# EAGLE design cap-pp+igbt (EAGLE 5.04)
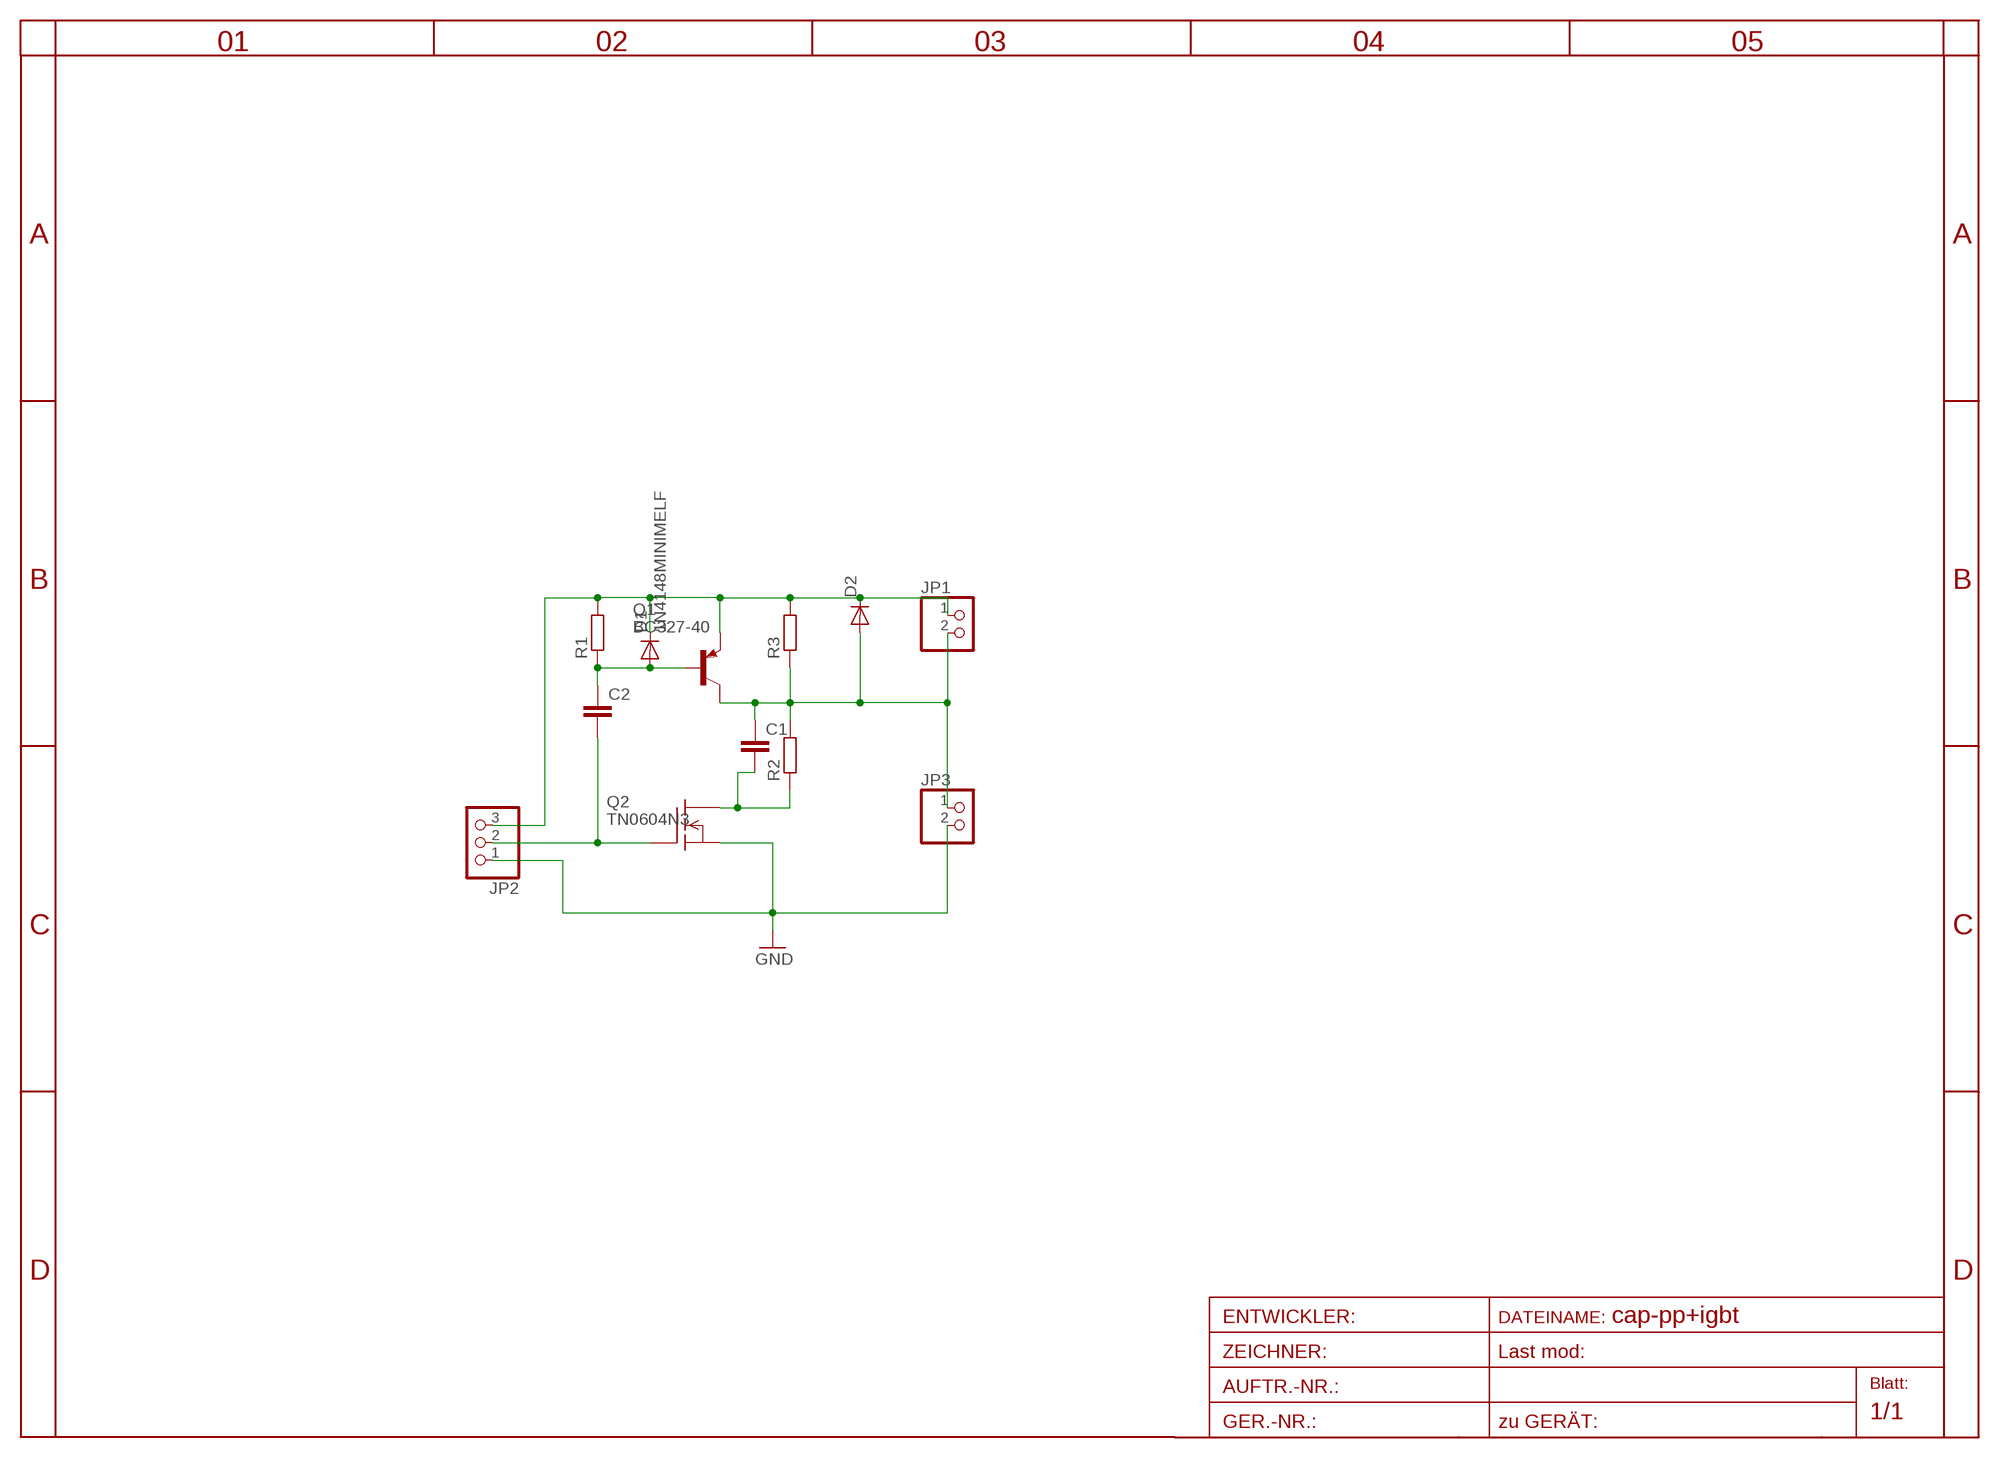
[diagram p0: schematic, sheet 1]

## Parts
C1  C-EU025_050-025X075  [C025_050-025X075]
C2  C-EU025_050-025X075  [C025_050-025X075]
D1  1N4148MINIMELF  [MINIMELF]
D2  DIODE-D-5  [D-5]
JP1  PINHD-1X2  [1X02]
JP2  PINHD-1X3  [1X03]
JP3  PINHD-1X2  [1X02]
Q1  BC327-40  [TO92-EBC]
Q2  TN0604N3  [TO-92]
R1  R-EU_0204/2V  [0204V]
R2  R-EU_0204/2V  [0204V]
R3  R-EU_0204/2V  [0204V]

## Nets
BB: C2.2 JP2.2 Q2.2(G)
GND: JP2.1 JP3.2 Q2.1(S)
N$1: C1.2 Q2.3(D) R2.1
OUT: C1.1 D2.A JP1.2 JP3.1 Q1.C R2.2 R3.1
TB: C2.1 D1.A Q1.B R1.1
V+: D1.C D2.C JP1.1 JP2.3 Q1.E R1.2 R3.2

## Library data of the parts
C1 C2 = rcl-2:C-EU: CAPACITOR, European symbol
D1 = diode-1:1N4148: DIODE
D2 = diode-1:DIODE-: DIODE
JP1 JP3 = pinhead:PINHD-1X2: PIN HEADER
JP2 = pinhead:PINHD-1X3: PIN HEADER
Q1 = transistor-pnp:BC327*: PNP Transistror
Q2 = transistor-fet:TN0604N3: N-Channel Enhancement MOSFET 40V; 4A; 0,75Ohm
R1-R3 = rcl-2:R-EU_: RESISTOR, European symbol

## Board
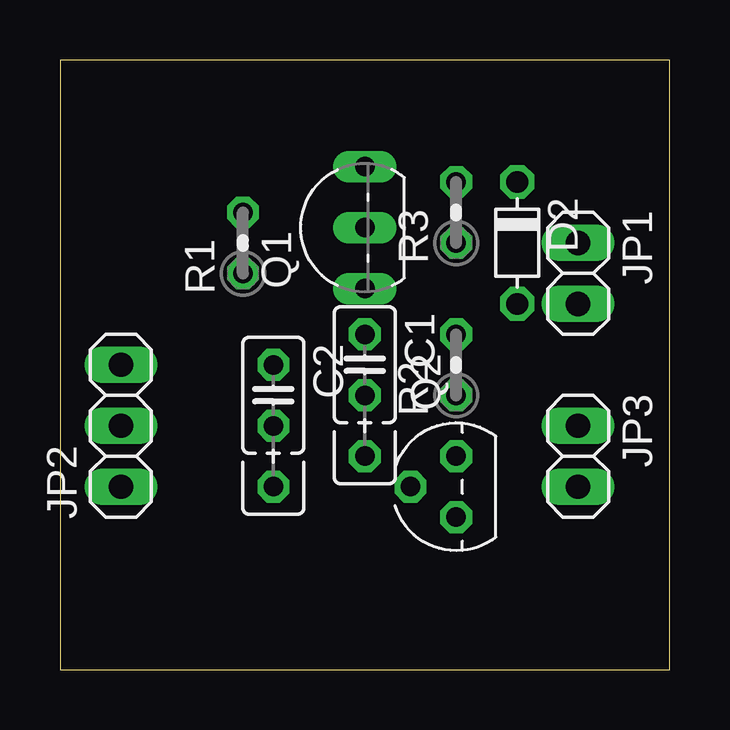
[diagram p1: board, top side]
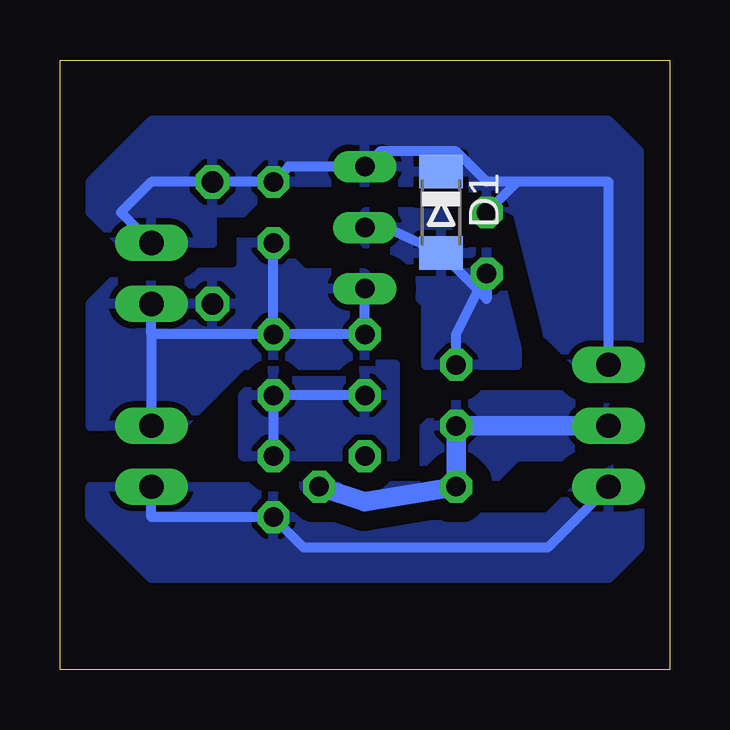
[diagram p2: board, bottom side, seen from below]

Size 25.4 x 25.4 mm. Coordinates in mm from the lower left corner, seen from the top.
Outline: 0,0 25.4,0 25.4,25.4 0,25.4 0,0
Copper layers (1*16): Top 0.035mm / dielectric 1.5mm / Bottom 0.035mm
Design rules "default": minimum track width 10mil, minimum drill 24mil, track to track 8mil, track to pad 8mil, pad to pad 8mil, via to via 8mil, smd to smd 8mil, copper to edge 40mil, drill to drill 8mil, minimum pad ring 10mil, minimum via ring 8mil, stop-mask expansion 4mil, vias tented up to drill 0mil, thermal gap 10mil

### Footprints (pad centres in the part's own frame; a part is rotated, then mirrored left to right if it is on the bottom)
C025_050-025X075 = drill 0.813 octagon: 1 -1.27,0; 2 1.27,0; 3 3.81,0
MINIMELF = smd 1.4 x 1.8: A 1.7,0; C -1.7,0
D-5 = drill 0.9 octagon: A 2.54,0; C -2.54,0
1X02 = drill 1.016 long: 1 -1.27,0; 2 1.27,0
1X03 = drill 1.016 long: 1 -2.54,0; 2 0,0; 3 2.54,0
TO92-EBC = drill 0.813 long: B 0,-1.27; C -2.54,-1.27; E 2.54,-1.27
TO-92 = drill 0.813 octagon: 1 -1.27,0; 2 0,1.905; 3 1.27,0
0204V = drill 0.813 octagon: 1 -1.27,0; 2 1.27,0

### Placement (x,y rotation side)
C1  12.7,12.7 270 top
C2  8.89,11.43 270 top
D1  9.53,19.05 270 bottom
D2  19.05,17.78 270 top
JP1  21.59,16.51 270 top
JP2  2.54,10.16 90 top
JP3  21.59,8.89 270 top
Q1  11.43,18.41 90 top
Q2  16.51,7.62 90 top
R1  7.62,17.78 90 top
R2  16.51,12.7 90 top
R3  16.51,19.05 90 top

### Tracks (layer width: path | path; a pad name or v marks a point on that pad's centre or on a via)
BB
  Bottom 0.813: JP2.2 C2.2 8.89,7.62 12.7,6.99 Q2.2
  pour Bottom (isolate 0.813, rank 4): 2.54,11.43 8.89,11.43 11.43,8.89 15.24,8.89 15.24,7.62 13.97,6.35 8.89,6.35 6.35,8.89 3.81,8.89
GND
  Bottom 0.406: JP2.1 5.08,5.08 15.24,5.08 Q2.1 21.59,6.35 JP3.2
  pour Bottom (isolate 0.813): 1.27,8.89 1.27,5.08 2.54,3.81 21.59,3.81 24.13,6.35 24.13,7.62 20.32,7.62 16.51,7.62 15.24,6.35 5.08,6.35 3.81,7.62
N$1
  Bottom 0.406: C1.2 R2.1 Q2.3
  pour Bottom (isolate 0.254, rank 3): 12.7,12.7 16.51,12.7 17.78,11.43 17.78,8.89 11.43,8.89 11.43,12.7
OUT
  Bottom 0.406: R2.2 21.59,13.97 | 21.59,13.97 JP1.2 | R2.2 C1.1 Q1.C | R2.2 R3.1 | 21.59,13.97 JP3.1
  pour Bottom (isolate 0.813, rank 2): 12.7,16.51 15.24,16.51 16.51,17.78 21.59,17.78 24.13,15.24 24.13,10.16 20.32,10.16 19.05,11.43 17.78,12.7 12.7,12.7
TB
  Bottom 0.406: C2.1 8.89,13.97 R1.1 7.62,15.45 D1.A 12.27,18.62 12.49,18.62 Q1.B
  pour Bottom (isolate 0.813, rank 3): 10.16,12.7 6.35,12.7 6.35,16.51 8.89,19.05 12.7,19.05 12.7,17.78 10.16,15.24
V+
  Bottom 0.406: JP2.3 2.54,20.32 6.35,20.32 | 6.35,20.32 7.62,20.32 8.89,21.59 10.16,21.59 | 10.16,21.59 12.06,21.59 Q1.E 15.88,20.95 R3.2 21.59,20.32 22.86,19.05 JP1.1 | D1.C 9.53,20.95 10.16,21.59 | 6.35,20.32 R1.2
  pour Bottom (isolate 0.813): 1.27,12.7 1.27,21.59 2.54,22.86 21.59,22.86 24.13,20.32 24.13,19.05 22.86,17.78 19.05,17.78 19.05,19.05 17.78,19.05 16.51,20.32 8.89,20.32 6.35,19.05 5.08,13.97 3.81,12.7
